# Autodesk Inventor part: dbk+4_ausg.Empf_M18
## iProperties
Shininess: 20.0
Length Units: 11269
Angle Units: 11279
Time Units: 11290
Mass Units: 11283
Length Display Precision: 2
Angle Display Precision: 2
Part Number: dbk+4_ausg.Empf_M18
Material: Nichtrostender Stahl - 440C
Document SubType Name: Modellieren
Description: dbk-4/Sender/M18/K2
Checked By: Alves
Created: 2005-08
Designer: Ohle
Manufacturer: Standard
Standards Organization: Custom
Density: 0.0
Volumn: 0.0
Area: 0.0
PropertySet Name: Model Information
Control State: 0
Master: False
Checked Out: False
BESTELLNUMMER: dbk-4/Sender/M18/K1
ME: ST
Title: dbk-4 Sensoren
Author: Ohle
Comments: keine Bemerkung
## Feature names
1. dbk-4 Sender [Revolution]
2. Extrusion6
3. Extrusion7
